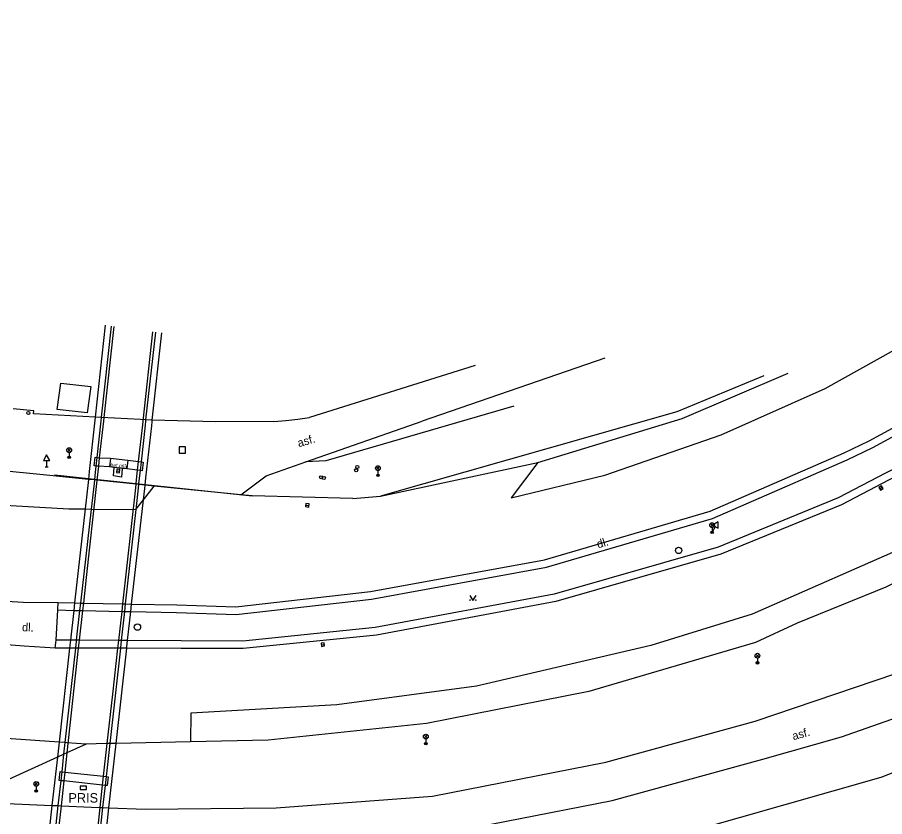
# Model space of a CAD drawing. Extents: x -602419 to -601554, y -1162937 to -1162362.
# Drawn here: x -601907 to -601838.6, y -1162441.4 to -1162378.3 of the extents above; entities that cross this region are included whole.
import ezdxf

# ---------------------------------------------------------------- set-up
doc = ezdxf.new("R2010")
doc.units = 0
doc.layers.add('Podklad', color=7, linetype='Continuous')

msp = doc.modelspace()

# ---------------------------------------------------------------- linework, layer by layer
at = {"layer": 'Podklad'}
for p, q in [((-601903.0725, -1162412.59), (-601902.8075, -1162412.325)), ((-601903.0725, -1162412.325), (-601902.8075, -1162412.59)), ((-601902.94, -1162412.645), (-601902.94, -1162413.02)), ((-601904.72, -1162413.261), (-601904.72, -1162413.77)), ((-601904.845, -1162413.77), (-601904.595, -1162413.77)), ((-601899.2043, -1162414.0865), (-601898.9557, -1162414.1135)), ((-601878.7125, -1162414.01), (-601878.4475, -1162413.745)), ((-601878.7125, -1162413.745), (-601878.4475, -1162414.01)), ((-601878.58, -1162414.065), (-601878.58, -1162414.44)), ((-601839.0075, -1162415.5138), (-601838.7925, -1162415.3862)), ((-601884.2737, -1162416.7918), (-601884.0263, -1162416.8282)), ((-601852.3524, -1162418.51), (-601852.0874, -1162418.245)), ((-601852.3524, -1162418.245), (-601852.0874, -1162418.51)), ((-601852.3282, -1162418.8775), (-601852.1116, -1162419.0025)), ((-601851.9654, -1162418.4992), (-601852.2199, -1162418.94)), ((-601852.2199, -1162418.565), (-601852.2199, -1162418.94)), ((-601883.0542, -1162427.8143), (-601882.8058, -1162427.7857)), ((-601848.7725, -1162428.81), (-601848.5075, -1162428.545)), ((-601848.7725, -1162428.545), (-601848.5075, -1162428.81)), ((-601848.64, -1162428.865), (-601848.64, -1162429.24)), ((-601874.9325, -1162435.19), (-601874.6675, -1162434.925)), ((-601874.9325, -1162434.925), (-601874.6675, -1162435.19)), ((-601874.8, -1162435.245), (-601874.8, -1162435.62)), ((-601905.6725, -1162438.93), (-601905.4075, -1162438.665)), ((-601905.6725, -1162438.665), (-601905.4075, -1162438.93)), ((-601905.54, -1162438.985), (-601905.54, -1162439.36))]:
    msp.add_line(p, q, dxfattribs=at)
for points in [[(-601865.9699, -1162413.44), (-601868.073, -1162416.225), (-601860.681, -1162414.433), (-601851.512, -1162411.249), (-601843.288, -1162407.585), (-601828.487, -1162399.344), (-601816.71, -1162390.08), (-601806.918, -1162379.855), (-601808.45, -1162378.3)], [(-601898.07, -1162425.19), (-601894.4699, -1162425.26), (-601889.76, -1162425.42), (-601879.08, -1162424.2199), (-601865.29, -1162421.68), (-601852.18, -1162417.85), (-601841.55, -1162413.2199), (-601839.55, -1162412.24), (-601835.86, -1162410.24), (-601830.12, -1162407.13), (-601824.77, -1162403.76), (-601820.58, -1162400.6599), (-601817.6, -1162398.25), (-601811.85, -1162393.6599), (-601811.18, -1162392.96), (-601804.44, -1162385.87)], [(-601802.7, -1162387.31), (-601802.79, -1162387.45), (-601806.1599, -1162391.14), (-601810.09, -1162395.04), (-601813.14, -1162397.9), (-601821.9099, -1162404.34), (-601823.6599, -1162405.63), (-601830.02, -1162409.87), (-601837.31, -1162413.64), (-601838.54, -1162414.28), (-601842.26, -1162416.2199), (-601851.73, -1162420.1), (-601864.69, -1162423.83), (-601878.79, -1162426.46), (-601889.23, -1162427.52), (-601894.11, -1162427.5), (-601898.33, -1162427.48)], [(-601797.24, -1162393.36), (-601799.042, -1162391.753), (-601806.692, -1162400.048), (-601817.129, -1162408.181), (-601826.438, -1162414.264), (-601836.254, -1162419.771), (-601849.065, -1162425.393), (-601857.06, -1162427.881), (-601870.816, -1162431.084), (-601881.829, -1162432.559), (-601893.35, -1162433.204), (-601893.374, -1162435.473)], [(-601812.75, -1162398.36), (-601823.35, -1162406.15), (-601829.71, -1162410.39), (-601837.31, -1162414.32), (-601838.26, -1162414.81), (-601842.01, -1162416.77), (-601851.54, -1162420.6599), (-601864.55, -1162424.4099), (-601878.7, -1162427.06), (-601889.2, -1162428.12), (-601894.11, -1162428.1), (-601898.4, -1162428.09)], [(-601898, -1162424.6), (-601894.45, -1162424.6599), (-601889.78, -1162424.82), (-601879.17, -1162423.62), (-601865.43, -1162421.1), (-601852.38, -1162417.28), (-601841.8, -1162412.68), (-601839.83, -1162411.71), (-601835.86, -1162409.56), (-601830.42, -1162406.61), (-601825.11, -1162403.27), (-601820.95, -1162400.18), (-601817.9699, -1162397.78)], [(-601900.1, -1162402.59), (-601900.88, -1162409.86)], [(-601900.38, -1162409.85), (-601899.6, -1162402.6599)], [(-601899.4099, -1162402.69), (-601900.21, -1162409.87)], [(-601897.11, -1162410.1599), (-601896.33, -1162403.12)], [(-601896.14, -1162403.14), (-601896.91, -1162410.06)], [(-601896.38, -1162410.08), (-601895.64, -1162403.21)], [(-601808.82, -1162404.4), (-601814.83, -1162409.42), (-601819.76, -1162412.82), (-601825.35, -1162416.38), (-601834.49, -1162421.29), (-601838.52, -1162423.27), (-601845.5, -1162426.1)], [(-601860.68, -1162405.19), (-601875.08, -1162410.18)], [(-601870.9, -1162405.78), (-601883.97, -1162409.88)], [(-601848.13, -1162406.58), (-601854.99, -1162409.43)], [(-601854.59, -1162409.97), (-601846.22, -1162406.38)], [(-601903.6, -1162407.17), (-601901.24, -1162407.42), (-601901.53, -1162409.51), (-601903.89, -1162409.26), (-601903.6, -1162407.17)], [(-601905.73, -1162409.35), (-601907.36, -1162409.19)], [(-601867.85, -1162408.98), (-601882.68, -1162413.3), (-601884.26, -1162413.38)], [(-601900.88, -1162409.86), (-601905.76, -1162409.59), (-601905.73, -1162409.35)], [(-601900.88, -1162409.86), (-601900.9099, -1162410.1)], [(-601900.38, -1162409.89), (-601900.88, -1162409.86)], [(-601900.4099, -1162410.15), (-601900.38, -1162409.89)], [(-601900.38, -1162409.89), (-601900.38, -1162409.85)], [(-601897.31, -1162410.05), (-601900.38, -1162409.89)], [(-601900.21, -1162409.87), (-601900.24, -1162410.17)], [(-601885.85, -1162410.11), (-601884.91, -1162410)], [(-601884.91, -1162410), (-601883.97, -1162409.88)], [(-601854.99, -1162409.43), (-601878.38, -1162416.08)], [(-601865.9699, -1162413.44), (-601854.59, -1162409.97)], [(-601900.9099, -1162410.1), (-601901.35, -1162414.13), (-601901.42, -1162414.76)], [(-601900.7199, -1162413.04), (-601900.4099, -1162410.15)], [(-601900.24, -1162410.17), (-601900.56, -1162413.05)], [(-601897.46, -1162413.36), (-601897.14, -1162410.46)], [(-601896.91, -1162410.06), (-601897.31, -1162410.05)], [(-601896.95, -1162410.48), (-601897.27, -1162413.38)], [(-601897.14, -1162410.46), (-601897.11, -1162410.1599)], [(-601896.92, -1162410.18), (-601896.95, -1162410.48)], [(-601896.95, -1162415.22), (-601896.88, -1162414.63), (-601896.43, -1162410.53)], [(-601896.91, -1162410.06), (-601896.92, -1162410.18)], [(-601896.38, -1162410.08), (-601896.91, -1162410.06)], [(-601896.43, -1162410.53), (-601896.4, -1162410.23)], [(-601896.4, -1162410.23), (-601896.38, -1162410.08)], [(-601886.8, -1162410.19), (-601891.39, -1162410.22), (-601896.38, -1162410.08)], [(-601889.4, -1162415.99), (-601887.41, -1162414.48), (-601884.26, -1162413.38), (-601875.08, -1162410.18)], [(-601886.8, -1162410.19), (-601885.85, -1162410.11)], [(-601900.9699, -1162413.7), (-601900.9, -1162413.02)], [(-601900.9, -1162413.02), (-601900.7199, -1162413.04)], [(-601900.8, -1162413.7199), (-601900.7199, -1162413.04)], [(-601900.7199, -1162413.04), (-601900.56, -1162413.05)], [(-601900.56, -1162413.05), (-601900.63, -1162413.73)], [(-601900.56, -1162413.05), (-601899.69, -1162413.09)], [(-601899.69, -1162413.09), (-601899.77, -1162413.78)], [(-601899.69, -1162413.09), (-601898.3, -1162413.24)], [(-601898.3, -1162413.24), (-601898.39, -1162413.93)], [(-601898.3, -1162413.24), (-601897.46, -1162413.36)], [(-601897.54, -1162414.04), (-601897.46, -1162413.36)], [(-601897.46, -1162413.36), (-601897.27, -1162413.38)], [(-601897.27, -1162413.38), (-601897.11, -1162413.4), (-601897.18, -1162414.08), (-601897.35, -1162414.06)], [(-601897.27, -1162413.38), (-601897.35, -1162414.06)], [(-601942.974, -1162413.752), (-601923.36, -1162415.7179), (-601914.899, -1162416.4019), (-601902.977, -1162417.0849), (-601901.6822, -1162417.0998), (-601901.1795, -1162417.1051), (-601901.1621, -1162417.1057), (-601897.689, -1162417.1448)], [(-601904.46, -1162414.45), (-601913.74, -1162413.53)], [(-601900.8, -1162413.7199), (-601900.9699, -1162413.7)], [(-601900.92, -1162414.81), (-601900.85, -1162414.19), (-601900.8, -1162413.7199)], [(-601900.63, -1162413.73), (-601900.8, -1162413.7199)], [(-601900.63, -1162413.73), (-601900.75, -1162414.83)], [(-601899.77, -1162413.78), (-601900.63, -1162413.73)], [(-601897.54, -1162414.04), (-601898.39, -1162413.93), (-601898.76, -1162413.9), (-601899.4, -1162413.82), (-601899.77, -1162413.78)], [(-601898.76, -1162413.9), (-601898.82, -1162414.59), (-601899.43, -1162414.49), (-601899.4, -1162413.82)], [(-601897.66, -1162415.15), (-601897.65, -1162415.07), (-601897.54, -1162414.04)], [(-601897.35, -1162414.06), (-601897.54, -1162414.04)], [(-601897.35, -1162414.06), (-601897.46, -1162415.09), (-601897.47, -1162415.17)], [(-601878.38, -1162416.08), (-601865.9699, -1162413.44)], [(-601900.92, -1162414.81), (-601901.42, -1162414.76), (-601904.46, -1162414.45)], [(-601904.09, -1162414.41), (-601901.41, -1162414.69)], [(-601901.42, -1162414.76), (-601901.45, -1162415.02)], [(-601901.41, -1162414.69), (-601896.94, -1162415.16)], [(-601901.45, -1162415.02), (-601901.6822, -1162417.0998), (-601902.51, -1162424.51)], [(-601902.02, -1162424.52), (-601901.1795, -1162417.1051), (-601900.95, -1162415.08)], [(-601900.78, -1162415.1), (-601901.6, -1162422.5), (-601901.82, -1162424.52)], [(-601900.95, -1162415.08), (-601900.92, -1162414.81)], [(-601900.75, -1162414.83), (-601900.92, -1162414.81)], [(-601900.75, -1162414.83), (-601900.78, -1162415.1)], [(-601897.66, -1162415.15), (-601900.75, -1162414.83)], [(-601898.71, -1162424.59), (-601897.69, -1162415.44)], [(-601897.5, -1162415.45), (-601897.689, -1162417.1448), (-601898.52, -1162424.59)], [(-601898.01, -1162424.6), (-601897.0799, -1162416.3645), (-601896.98, -1162415.48)], [(-601897.69, -1162415.44), (-601897.66, -1162415.15)], [(-601897.689, -1162417.1448), (-601897.0799, -1162416.3645), (-601896.24, -1162415.29)], [(-601897.47, -1162415.17), (-601897.66, -1162415.15)], [(-601897.47, -1162415.17), (-601897.5, -1162415.45)], [(-601889.4, -1162415.99), (-601896.24, -1162415.29), (-601896.95, -1162415.22), (-601897.47, -1162415.17)], [(-601896.98, -1162415.48), (-601896.95, -1162415.22)], [(-601896.94, -1162415.16), (-601888.49, -1162416.05)], [(-601880.55, -1162416.27), (-601888.49, -1162416.05), (-601889.4, -1162415.99)], [(-601880.55, -1162416.27), (-601878.38, -1162416.08)], [(-601893.37, -1162444.62), (-601884.84, -1162446.24), (-601877.27, -1162446.73), (-601857.63, -1162443.6), (-601838.87, -1162438.26), (-601825.21, -1162432.93), (-601808.38, -1162416.6599)], [(-601848.2199, -1162436.84), (-601842, -1162435.09), (-601837.07, -1162433.34), (-601833.53, -1162431.9), (-601829.8, -1162430.19), (-601826.44, -1162428.48), (-601821.73, -1162425.7), (-601816.42, -1162422.27), (-601812.33, -1162419.46), (-601808.38, -1162416.6599)], [(-601915.7199, -1162423.81), (-601908.74, -1162424.31), (-601906.58, -1162424.44), (-601903.8, -1162424.49), (-601902.51, -1162424.51)], [(-601871.34, -1162423.935), (-601871.09, -1162424.31), (-601870.84, -1162423.935)], [(-601901.6, -1162435.65), (-601903.1262, -1162435.5438), (-601903.2493, -1162435.535), (-601903.7384, -1162435.5009), (-601945.81, -1162432.57), (-601944.69, -1162424.95)], [(-601903.84, -1162425.07), (-601903.8, -1162424.49)], [(-601902.51, -1162424.51), (-601902.58, -1162425.1)], [(-601902.51, -1162424.51), (-601902.02, -1162424.52)], [(-601902.09, -1162425.11), (-601902.02, -1162424.52)], [(-601902.02, -1162424.52), (-601901.82, -1162424.52)], [(-601901.82, -1162424.52), (-601901.89, -1162425.11)], [(-601901.82, -1162424.52), (-601898.71, -1162424.59)], [(-601898.77, -1162425.18), (-601898.71, -1162424.59)], [(-601898.71, -1162424.59), (-601898.52, -1162424.59)], [(-601898.52, -1162424.59), (-601898.58, -1162425.18)], [(-601898.52, -1162424.59), (-601898.01, -1162424.6)], [(-601898.08, -1162425.19), (-601898.01, -1162424.6)], [(-601898.01, -1162424.6), (-601898, -1162424.6)], [(-601903.96, -1162427.45), (-601903.84, -1162425.07), (-601902.58, -1162425.1)], [(-601902.58, -1162425.1), (-601902.84, -1162427.46)], [(-601902.58, -1162425.1), (-601902.57, -1162425.1)], [(-601902.57, -1162425.1), (-601902.09, -1162425.11)], [(-601902.35, -1162427.46), (-601902.09, -1162425.11)], [(-601901.89, -1162425.11), (-601902.15, -1162427.46)], [(-601902.09, -1162425.11), (-601901.89, -1162425.11)], [(-601901.89, -1162425.11), (-601898.77, -1162425.18)], [(-601899.03, -1162427.48), (-601898.77, -1162425.18)], [(-601898.58, -1162425.18), (-601898.84, -1162427.48)], [(-601898.77, -1162425.18), (-601898.58, -1162425.18)], [(-601898.58, -1162425.18), (-601898.08, -1162425.19)], [(-601898.33, -1162427.48), (-601898.08, -1162425.19)], [(-601898.08, -1162425.19), (-601898.07, -1162425.19)], [(-601845.5, -1162426.1), (-601848.8, -1162427.64)], [(-601902.9099, -1162428.07), (-601904.04, -1162428.07), (-601906.5, -1162427.92), (-601908.93, -1162427.75), (-601916.05, -1162427.25)], [(-601904.04, -1162428.07), (-601903.96, -1162427.45)], [(-601902.84, -1162427.46), (-601903.96, -1162427.45)], [(-601902.84, -1162427.46), (-601902.9099, -1162428.07)], [(-601902.35, -1162427.46), (-601902.84, -1162427.46)], [(-601902.42, -1162428.07), (-601902.36, -1162427.54), (-601902.35, -1162427.46)], [(-601902.15, -1162427.46), (-601902.35, -1162427.46)], [(-601902.15, -1162427.46), (-601902.2199, -1162428.07)], [(-601899.03, -1162427.48), (-601902.15, -1162427.46)], [(-601899.1, -1162428.09), (-601899.03, -1162427.48)], [(-601898.84, -1162427.48), (-601899.03, -1162427.48)], [(-601898.84, -1162427.48), (-601898.9, -1162428.05), (-601898.9, -1162428.09)], [(-601898.33, -1162427.48), (-601898.84, -1162427.48)], [(-601898.4, -1162428.09), (-601898.39, -1162427.98), (-601898.33, -1162427.48)], [(-601848.8, -1162427.64), (-601861.94, -1162431.51)], [(-601902.9099, -1162428.07), (-601903.7384, -1162435.5009), (-601903.87, -1162436.68)], [(-601903.35, -1162436.44), (-601903.2493, -1162435.535), (-601902.42, -1162428.07)], [(-601902.2199, -1162428.07), (-601903.12, -1162436.34)], [(-601902.42, -1162428.07), (-601902.9099, -1162428.07)], [(-601902.2199, -1162428.07), (-601902.42, -1162428.07)], [(-601899.1, -1162428.09), (-601902.2199, -1162428.07)], [(-601899.93, -1162435.61), (-601899.5, -1162431.7199), (-601899.1, -1162428.09)], [(-601898.9, -1162428.09), (-601899.74, -1162435.61)], [(-601899.24, -1162435.6), (-601898.4, -1162428.09)], [(-601898.9, -1162428.09), (-601899.1, -1162428.09)], [(-601898.4, -1162428.09), (-601898.9, -1162428.09)], [(-601848.83, -1162433.85), (-601834.62, -1162429.02)], [(-601861.94, -1162431.51), (-601874.76, -1162434.02)], [(-601899.8, -1162440.68), (-601896.94, -1162440.8), (-601886.6, -1162440.69), (-601874.27, -1162439.75), (-601860.59, -1162437.07), (-601848.83, -1162433.85)], [(-601874.76, -1162434.02), (-601887.23, -1162435.34)], [(-601901.6, -1162435.65), (-601903.12, -1162436.34)], [(-601900.81, -1162435.63), (-601901.6, -1162435.65)], [(-601899.93, -1162435.61), (-601900.81, -1162435.63)], [(-601900.2199, -1162438.19), (-601899.93, -1162435.61)], [(-601899.74, -1162435.61), (-601900.03, -1162438.21)], [(-601899.74, -1162435.61), (-601899.93, -1162435.61)], [(-601899.8, -1162440.68), (-601899.24, -1162435.6)], [(-601899.24, -1162435.6), (-601899.74, -1162435.61)], [(-601887.23, -1162435.34), (-601893.374, -1162435.473), (-601899.24, -1162435.6)], [(-601903.87, -1162436.68), (-601907.73, -1162438.44)], [(-601903.87, -1162436.68), (-601904.3, -1162440.49)], [(-601903.35, -1162436.44), (-601903.87, -1162436.68)], [(-601903.5, -1162437.84), (-601903.35, -1162436.44)], [(-601903.12, -1162436.34), (-601903.35, -1162436.44)], [(-601903.12, -1162436.34), (-601903.29, -1162437.86)], [(-601900.13, -1162443.68), (-601897.13, -1162443.81), (-601886.86, -1162443.74), (-601884.7199, -1162443.68), (-601874.48, -1162442.92), (-601860.1, -1162440.1), (-601848.2199, -1162436.84)], [(-601903.74, -1162438.52), (-601903.6599, -1162437.82)], [(-601903.6599, -1162437.82), (-601903.5, -1162437.84)], [(-601903.58, -1162438.54), (-601903.5, -1162437.84)], [(-601903.5, -1162437.84), (-601903.29, -1162437.86)], [(-601903.29, -1162437.86), (-601903.37, -1162438.56)], [(-601903.29, -1162437.86), (-601900.2199, -1162438.19)], [(-601903.8, -1162440.51), (-601903.58, -1162438.54)], [(-601903.58, -1162438.54), (-601903.74, -1162438.52)], [(-601903.37, -1162438.56), (-601903.58, -1162438.54)], [(-601903.37, -1162438.56), (-601903.58, -1162440.52)], [(-601900.3, -1162438.89), (-601903.37, -1162438.56)], [(-601900.3, -1162438.89), (-601900.2199, -1162438.19)], [(-601900.2199, -1162438.19), (-601900.03, -1162438.21)], [(-601900.03, -1162438.21), (-601899.87, -1162438.23), (-601899.95, -1162438.93), (-601900.11, -1162438.9099)], [(-601900.03, -1162438.21), (-601900.11, -1162438.9099)], [(-601900.49, -1162440.65), (-601900.3, -1162438.89)], [(-601900.11, -1162438.9099), (-601900.3, -1162438.89)], [(-601900.11, -1162438.9099), (-601900.3, -1162440.6599)], [(-601909.62, -1162440.26), (-601904.3, -1162440.49)], [(-601904.3, -1162440.49), (-601904.63, -1162443.48)], [(-601904.3, -1162440.49), (-601903.8, -1162440.51)], [(-601904.13, -1162443.5), (-601903.8, -1162440.51)], [(-601903.58, -1162440.52), (-601903.9099, -1162443.51)], [(-601903.8, -1162440.51), (-601903.58, -1162440.52)], [(-601903.58, -1162440.52), (-601901.17, -1162440.62)], [(-601901.17, -1162440.62), (-601900.49, -1162440.65)], [(-601900.82, -1162443.65), (-601900.49, -1162440.65)], [(-601900.3, -1162440.6599), (-601900.63, -1162443.6599)], [(-601900.49, -1162440.65), (-601900.3, -1162440.6599)], [(-601900.3, -1162440.6599), (-601899.8, -1162440.68)], [(-601900.13, -1162443.68), (-601899.8, -1162440.68)]]:
    msp.add_lwpolyline(points, dxfattribs=at)
for points in [[(-601894.26, -1162412.69), (-601893.76, -1162412.69), (-601893.76, -1162412.19), (-601894.26, -1162412.19)], [(-601904.97, -1162413.261), (-601904.47, -1162413.261), (-601904.72, -1162412.828)], [(-601899.2178, -1162414.2107), (-601898.9693, -1162414.2378), (-601898.9422, -1162413.9893), (-601899.1907, -1162413.9622)], [(-601838.9437, -1162415.6213), (-601838.7287, -1162415.4937), (-601838.8563, -1162415.2787), (-601839.0713, -1162415.4063)], [(-601884.2919, -1162416.9154), (-601884.0446, -1162416.9519), (-601884.0081, -1162416.7046), (-601884.2554, -1162416.6681)], [(-601852.1819, -1162418.3742), (-601851.7489, -1162418.6242), (-601851.7489, -1162418.1242)], [(-601883.0398, -1162427.9385), (-601882.7915, -1162427.9098), (-601882.8202, -1162427.6615), (-601883.0685, -1162427.6902)], [(-601902.06, -1162439.225), (-601901.56, -1162439.225), (-601901.56, -1162438.975), (-601902.06, -1162438.975)]]:
    msp.add_lwpolyline(points, close=True, dxfattribs=at)
for centre, radius in [((-601906.16, -1162409.53), 0.125), ((-601902.94, -1162412.4575), 0.1875), ((-601902.94, -1162413.02), 0.1), ((-601902.94, -1162413.02), 0.0723), ((-601902.94, -1162413.02), 0.0438), ((-601880.3, -1162414.04), 0.125), ((-601880.21, -1162413.79), 0.125), ((-601878.58, -1162413.8775), 0.1875), ((-601883.06, -1162414.6), 0.125), ((-601882.85, -1162414.65), 0.125), ((-601878.58, -1162414.44), 0.1), ((-601878.58, -1162414.44), 0.0723), ((-601878.58, -1162414.44), 0.0438), ((-601852.2199, -1162418.3775), 0.1875), ((-601852.2199, -1162418.94), 0.1), ((-601852.2199, -1162418.94), 0.0723), ((-601852.2199, -1162418.94), 0.0438), ((-601854.86, -1162420.37), 0.25), ((-601871.3151, -1162424.2849), 0.025), ((-601870.8654, -1162424.2849), 0.025), ((-601897.55, -1162426.42), 0.25), ((-601848.64, -1162428.6775), 0.1875), ((-601848.64, -1162429.24), 0.1), ((-601848.64, -1162429.24), 0.0723), ((-601848.64, -1162429.24), 0.0438), ((-601874.8, -1162435.0575), 0.1875), ((-601874.8, -1162435.62), 0.1), ((-601874.8, -1162435.62), 0.0723), ((-601874.8, -1162435.62), 0.0438), ((-601905.54, -1162438.7975), 0.1875), ((-601905.54, -1162439.36), 0.1), ((-601905.54, -1162439.36), 0.0723), ((-601905.54, -1162439.36), 0.0438)]:
    msp.add_circle(centre, radius, dxfattribs=at)

# ---------------------------------------------------------------- texts
for s, height, rotation, p in [('asf.', 0.65, 16.397899, (-601884.82, -1162412.23)), ('bet.pilíř', 0.3, 353.802078, (-601899.7, -1162413.75)), ('dl.', 0.65, 16.29, (-601861.21, -1162420.21)), ('dl.', 0.65, 357.55, (-601906.67, -1162426.74)), ('asf.', 0.65, 15.34, (-601845.8, -1162435.35))]:
    msp.add_text(s, height=height, rotation=rotation, dxfattribs=at).set_placement(p)
msp.add_text('PRIS', height=0.75, dxfattribs=at).set_placement((-601903, -1162440.27))

doc.saveas('drawing.dxf')
